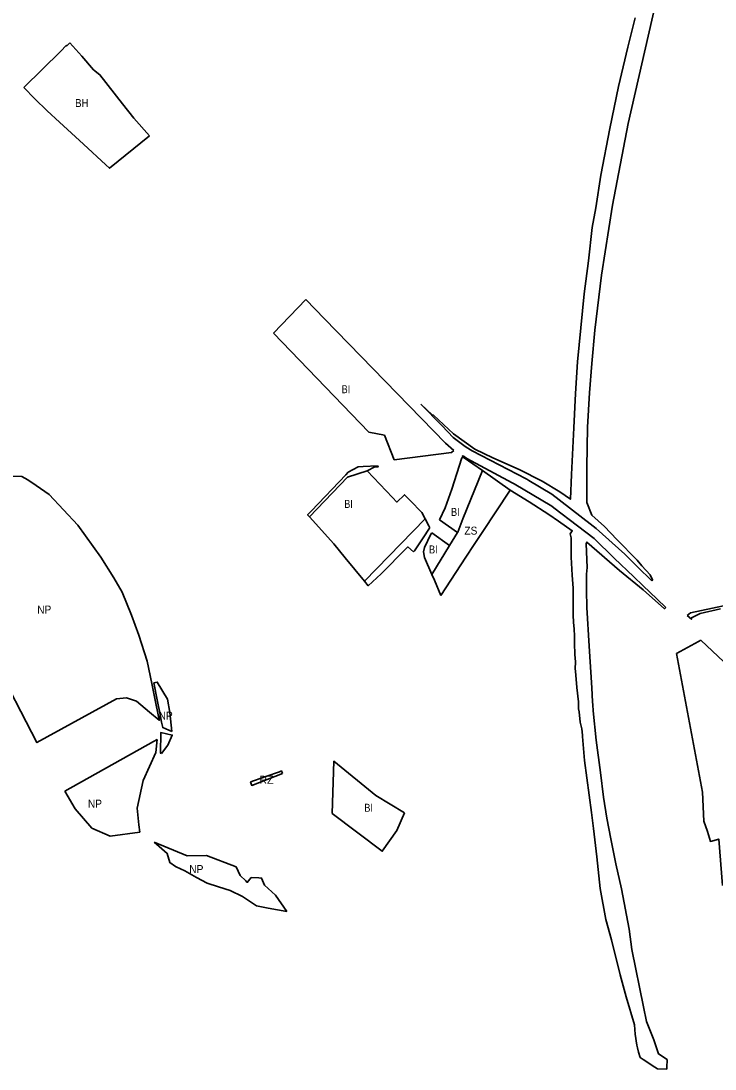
# Model space of a CAD drawing. Extents: x -650971 to -642489, y -1074311 to -1062745.
# Drawn here: x -646196 to -645155, y -1073293 to -1071722 of the extents above; entities that cross this region are included whole.
import ezdxf

# ---------------------------------------------------------------- set-up
doc = ezdxf.new("R2010")
doc.units = 0
doc.header["$LTSCALE"] = 4.8
for name, color, linetype, lineweight in [('1', 7, 'Continuous', 35), ('15', 7, 'Continuous', 35), ('19', 7, 'Continuous', 35), ('2', 7, 'Continuous', 35), ('24', 7, 'Continuous', 35), ('41', 7, 'Continuous', 35), ('48', 7, 'Continuous', 35), ('6', 7, 'Continuous', 35), ('62', 7, 'Continuous', 35)]:
    doc.layers.add(name, color=color, linetype=linetype, lineweight=lineweight)

msp = doc.modelspace()

# ---------------------------------------------------------------- linework, layer by layer
at = {"layer": '1'}
for points in [[(-646191.57, -1071821.44), (-646136.12, -1071767.07), (-646127.84, -1071758.53), (-646127.12, -1071759.15), (-646122.16, -1071754.78)], [(-646122.16, -1071754.78), (-646104.5, -1071774.86), (-646087, -1071795), (-646077.32, -1071802.59), (-646043.49, -1071845.87), (-646026.64, -1071867.44), (-646002.93, -1071893.984)], [(-646068.317, -1071937.555), (-646102.04, -1071906.4), (-646137.74, -1071873.31), (-646156.59, -1071856.53), (-646174.69, -1071838.69), (-646191.57, -1071821.44)], [(-646002.93, -1071893.984), (-646062.91, -1071942.55), (-646068.317, -1071937.555)]]:
    msp.add_lwpolyline(points, dxfattribs=at)
at = {"layer": '15'}
for p, q in [((-645680.87, -1072561.42), (-645589.862, -1072468.109)), ((-645197.044, -1072612.821), (-645192.06, -1072609.19))]:
    msp.add_line(p, q, dxfattribs=at)
for points in [[(-645763.06, -1072465.26), (-645765.95, -1072462.03), (-645760.02, -1072455.94), (-645708.94, -1072402.11), (-645705, -1072398.19), (-645690.37, -1072390.13), (-645682.59, -1072389.76), (-645661.3, -1072388.74)], [(-645661.3, -1072388.74), (-645660.16, -1072389.95), (-645665.32, -1072390.32), (-645676.53, -1072396.16)], [(-645676.53, -1072396.16), (-645706.039, -1072405.769), (-645763.06, -1072465.26)], [(-645589.862, -1072468.109), (-645584.46, -1072478.58), (-645582.84, -1072481.71)], [(-645582.84, -1072481.71), (-645583.13, -1072482.13), (-645592.9, -1072496.52), (-645604.82, -1072514.3), (-645605.95, -1072515.95), (-645607.07, -1072517.61)], [(-645607.07, -1072517.61), (-645615.95, -1072510.16), (-645617.87, -1072512.12), (-645655.65, -1072550.62), (-645675.13, -1072568.36), (-645680.87, -1072561.42)], [(-645192.06, -1072609.19), (-645102.73, -1072589.74), (-644999.72, -1072564.24), (-644978.56, -1072558.74), (-644967.97, -1072556.17), (-644954.57, -1072554.43), (-644946.57, -1072554.22), (-644926.81, -1072552.51)], [(-645147.13, -1072602.79), (-645177.56, -1072609.89), (-645179.6, -1072610.94), (-645190.59, -1072616.28), (-645190.71, -1072618.6), (-645197.044, -1072612.821)]]:
    msp.add_lwpolyline(points, dxfattribs=at)
at = {"layer": '19'}
for points in [[(-645213.34, -1072669.98), (-645180.05, -1072651.77), (-645176.71, -1072650.01)], [(-645176.71, -1072650.01), (-645142.1, -1072682.57), (-645133.26, -1072694.17), (-645121.96, -1072711.68), (-645076.66, -1072783.06)], [(-645144.37, -1073017.64), (-645149.84, -1072948.13), (-645162.379, -1072951.55), (-645166.48, -1072936.5), (-645172.28, -1072921.42), (-645174.13, -1072877.93), (-645213.34, -1072669.98)]]:
    msp.add_lwpolyline(points, dxfattribs=at)
at = {"layer": '2'}
msp.add_line((-645817.219, -1072189.975), (-645768.649, -1072139.283), dxfattribs=at)
for points in [[(-645768.649, -1072139.283), (-645740.45, -1072168.23), (-645559.34, -1072354.42), (-645546.82, -1072365.72)], [(-645636.37, -1072379.57), (-645650.78, -1072342.73), (-645674, -1072338), (-645817.219, -1072189.975)], [(-645546.82, -1072365.72), (-645550.41, -1072368.47), (-645636.37, -1072379.57)], [(-645568.38, -1072469.68), (-645559.92, -1072451.41), (-645549.6, -1072423.39), (-645535.05, -1072376.72), (-645532.75, -1072375.41), (-645503.98, -1072395.64)], [(-645763.06, -1072465.26), (-645706.039, -1072405.769), (-645676.53, -1072396.16)], [(-645676.53, -1072396.16), (-645638.82, -1072435.99), (-645632.1, -1072442.93), (-645620.56, -1072432), (-645609.99, -1072443.22), (-645597.15, -1072456.15), (-645597.122, -1072456.121), (-645594.83, -1072458.48), (-645589.862, -1072468.109), (-645680.87, -1072561.42)], [(-645503.98, -1072395.64), (-645533.15, -1072468.21), (-645541.09, -1072487.98), (-645541.56, -1072488.74), (-645568.38, -1072469.68)], [(-645680.87, -1072561.42), (-645709.92, -1072526.3), (-645726.95, -1072505.7), (-645763.06, -1072465.26)], [(-645579.76, -1072551.45), (-645591.03, -1072526.14), (-645592.08, -1072517.43), (-645591.06, -1072511.06), (-645581.13, -1072491), (-645579.92, -1072489.22)], [(-645579.92, -1072489.22), (-645553.35, -1072508.1), (-645579.76, -1072551.45)], [(-645729.36, -1072909.65), (-645726.9, -1072831.5), (-645663.52, -1072882.58), (-645620.92, -1072908.65)], [(-645620.92, -1072908.65), (-645632.23, -1072935.28), (-645654.16, -1072966.3), (-645729.36, -1072909.65)]]:
    msp.add_lwpolyline(points, dxfattribs=at)
at = {"layer": '24'}
for points in [[(-645244.798, -1071696.585), (-645285.617, -1071875.733), (-645309.01, -1071998.147), (-645325.498, -1072102.789), (-645335.367, -1072185.207), (-645339.908, -1072235.158), (-645343.458, -1072278.998), (-645346.62, -1072330.914), (-645347.677, -1072391.355), (-645347.551, -1072443.527), (-645339.904, -1072462.677), (-645320.805, -1072479.495), (-645302.303, -1072499.014), (-645272.276, -1072530.154), (-645265.009, -1072538.358)], [(-645596.405, -1072296.114), (-645579.217, -1072312.425), (-645577.33, -1072312.704), (-645547.593, -1072340.827), (-645515.437, -1072363.447), (-645488.64, -1072376.782), (-645448.831, -1072394.325), (-645414.631, -1072411.611), (-645387.894, -1072427.453), (-645372.228, -1072438.764), (-645370.624, -1072401.447), (-645366.951, -1072331.609), (-645364.435, -1072280.268), (-645361.317, -1072232.824), (-645351.358, -1072130.815), (-645344.819, -1072081.225), (-645339.455, -1072031.565), (-645334.118, -1072001.954), (-645326.343, -1071952.807), (-645313.153, -1071883.081), (-645300.076, -1071820.179), (-645286.175, -1071761.228), (-645274.868, -1071717.176)], [(-645249.9, -1072561.25), (-645271.74, -1072539.96), (-645290.76, -1072520.92), (-645333.62, -1072482.33), (-645342.284, -1072475.625), (-645399.77, -1072431.12), (-645434.19, -1072410.67), (-645437.6, -1072408.64), (-645438.64, -1072408.1), (-645519.57, -1072366.3), (-645528.27, -1072360.53), (-645531.65, -1072358.29), (-645532.07, -1072358.01), (-645547.72, -1072346.19), (-645564.4, -1072328.61), (-645596.405, -1072296.114)], [(-645532.75, -1072375.41), (-645534.3, -1072374.33), (-645533.08, -1072373.71)], [(-645533.08, -1072373.71), (-645527.33, -1072377.73), (-645459.31, -1072413.95), (-645456.52, -1072415.6), (-645400.12, -1072449.03), (-645396.94, -1072451.44), (-645361.47, -1072478.388), (-645336.33, -1072497.48), (-645306.46, -1072527.08), (-645276.93, -1072555.11), (-645263.7, -1072567.8), (-645242, -1072588.6), (-645228.96, -1072600.865)], [(-645462.651, -1072425.011), (-645462.65, -1072425.01), (-645503.98, -1072395.64), (-645532.75, -1072375.41)], [(-645359.825, -1072751.964), (-645359.96, -1072742.38), (-645362.37, -1072720.66), (-645364.5, -1072696.22), (-645364.786, -1072692.977), (-645364.524, -1072682.575), (-645365.24, -1072671.66), (-645366.02, -1072654.46), (-645366.09, -1072643.58), (-645366.41, -1072633.54), (-645367.25, -1072622.73), (-645368.04, -1072612.42), (-645367.78, -1072602.42), (-645368.173, -1072571.881), (-645369.31, -1072552.64), (-645370.22, -1072543.37), (-645370.755, -1072525.734), (-645370.928, -1072496.619), (-645372.72, -1072490.314), (-645369.364, -1072485.931), (-645389.731, -1072471.612), (-645404.64, -1072461.72), (-645433.91, -1072442.56), (-645462.651, -1072425.011)], [(-645228.96, -1072600.865), (-645230.845, -1072602.888), (-645263.217, -1072574.314), (-645298.498, -1072545.352), (-645347.292, -1072502.877), (-645348.253, -1072505.583), (-645347.214, -1072540.97), (-645347.88, -1072551.13), (-645347.795, -1072577.893), (-645347.37, -1072597.96), (-645347.3, -1072601.13), (-645344.152, -1072658.857), (-645339.96, -1072721.587), (-645338.778, -1072742.565), (-645338.538, -1072746.821)], [(-645265.009, -1072538.358), (-645252.768, -1072552.178), (-645248.967, -1072559.511), (-645249.9, -1072561.25)], [(-645338.538, -1072746.821), (-645338.023, -1072755.969), (-645333.718, -1072799.987), (-645327.091, -1072848.387), (-645322.284, -1072885.085), (-645317.65, -1072916.642), (-645311.772, -1072947.945), (-645304.24, -1072985.372), (-645295.788, -1073022.556), (-645284.269, -1073083.286), (-645279.878, -1073113.356), (-645262.388, -1073199.409), (-645257.842, -1073221.36), (-645247.051, -1073248.736), (-645239.9, -1073270.025), (-645226.847, -1073278.345)], [(-645359.179, -1072757.517), (-645359.76, -1072752.865), (-645359.825, -1072751.964)], [(-645355.121, -1072782.993), (-645357.272, -1072772.771), (-645359.179, -1072757.517)], [(-645353.861, -1072794.334), (-645354.019, -1072792.454), (-645355.121, -1072782.993)], [(-645332.517, -1072974.538), (-645337.34, -1072932.073), (-645340.345, -1072908.029), (-645350.822, -1072830.388), (-645353.86, -1072794.339), (-645353.861, -1072794.334)], [(-645310.558, -1073098.946), (-645319.052, -1073068.6), (-645327.554, -1073022.214), (-645332.517, -1072974.538)], [(-645272.747, -1073256.762), (-645275.269, -1073240.71), (-645276.125, -1073226.571), (-645288.647, -1073184.518), (-645297.395, -1073151.294), (-645310.558, -1073098.946)], [(-645267.53, -1073275.44), (-645269.83, -1073267.22), (-645271.52, -1073261.16), (-645272.747, -1073256.762)], [(-645227.744, -1073292.736), (-645241.72, -1073292.2), (-645245.5, -1073289.73), (-645263.03, -1073278.25), (-645267.53, -1073275.44)], [(-645226.847, -1073278.345), (-645227.199, -1073283.366), (-645227.35, -1073285.55), (-645227.744, -1073292.736)]]:
    msp.add_lwpolyline(points, dxfattribs=at)
at = {"layer": '41'}
for points in [[(-645541.56, -1072488.74), (-645541.09, -1072487.98), (-645533.15, -1072468.21), (-645503.98, -1072395.64)], [(-645503.98, -1072395.64), (-645462.65, -1072425.01), (-645462.651, -1072425.011)], [(-645462.651, -1072425.011), (-645504.48, -1072488.58), (-645516.37, -1072506.64), (-645528.81, -1072525.54), (-645566.54, -1072582.88)], [(-645579.76, -1072551.45), (-645553.35, -1072508.1), (-645541.56, -1072488.74)], [(-645566.54, -1072582.88), (-645575.9, -1072560.13), (-645579.76, -1072551.45)]]:
    msp.add_lwpolyline(points, dxfattribs=at)
at = {"layer": '48'}
for points in [[(-646237.94, -1072404.35), (-646194.19, -1072404.62), (-646185.45, -1072409.47), (-646172.81, -1072418.2), (-646153.49, -1072431.54), (-646110.61, -1072477.49), (-646075.82, -1072525.54), (-646056.42, -1072556.49), (-646043.87, -1072578.12), (-646030.17, -1072612.31), (-646019.16, -1072642.35), (-646006.66, -1072681.4), (-645999.25, -1072714.68), (-645993.89, -1072742.23), (-645990.04, -1072761.78), (-645988.43, -1072769.93), (-646003.22, -1072757.85), (-646022.4, -1072741.58), (-646037.23, -1072736.38), (-646052.58, -1072737.82), (-646171.72, -1072803.51), (-646236.97, -1072678.31)], [(-646129.91, -1072876.24), (-645996.8, -1072801.88), (-645991.37, -1072798.84)], [(-645991.37, -1072798.84), (-645993.47, -1072818.44), (-646012.37, -1072860.3), (-646021.64, -1072901.6), (-646019.21, -1072926.91), (-646017.65, -1072937.59)], [(-646089.39, -1072931.92), (-646114.5, -1072902.8), (-646129.91, -1072876.24)], [(-646017.65, -1072937.59), (-646062.04, -1072943.58), (-646089.39, -1072931.92)], [(-645996.2, -1072952.69), (-645946.4, -1072973.05), (-645917.53, -1072972.93), (-645873.3, -1072989.79), (-645866.93, -1073002.72), (-645858.82, -1073010.74), (-645856.46, -1073013.07), (-645850.37, -1073005.42), (-645838.89, -1073006.18), (-645834.9, -1073006.45), (-645830.6, -1073016.92), (-645814.27, -1073032.11), (-645797.32, -1073056.62)], [(-645797.32, -1073056.62), (-645824.93, -1073051.83), (-645842.53, -1073048.19), (-645863.39, -1073034.25), (-645882.07, -1073025.22), (-645899.35, -1073019.65), (-645916.47, -1073014.03), (-645932.44, -1073005.5), (-645949.85, -1072995.57), (-645962.81, -1072989.45), (-645963.77, -1072989), (-645972.6, -1072983.41), (-645976.48, -1072969.55), (-645988.49, -1072959.28), (-645996.2, -1072952.69)]]:
    msp.add_lwpolyline(points, dxfattribs=at)
for points in [[(-645969.46, -1072787.03), (-645983.22, -1072780.88), (-645984.79, -1072772.91), (-645987.1, -1072761.2), (-645990.95, -1072741.65), (-645996.31, -1072714.11), (-645991.31, -1072712.86), (-645975.86, -1072738.61), (-645972.31, -1072758.48)], [(-645985.19, -1072819.72), (-645986.71, -1072819.26), (-645986.24, -1072788.33), (-645969.01, -1072792.28), (-645975.3, -1072807.37)]]:
    msp.add_lwpolyline(points, close=True, dxfattribs=at)
at = {"layer": '6'}
for points in [[(-645849.705, -1072867.618), (-645851.48, -1072862.586), (-645848.628, -1072861.433), (-645845.619, -1072860.364), (-645842.74, -1072859.344), (-645839.908, -1072858.343), (-645837.027, -1072857.313), (-645834.208, -1072856.314), (-645828.409, -1072854.254), (-645825.527, -1072853.233), (-645822.726, -1072852.233), (-645819.779, -1072851.184), (-645816.948, -1072850.184), (-645813.978, -1072849.124), (-645811.148, -1072848.124), (-645808.177, -1072847.063), (-645805.159, -1072845.994), (-645803.84, -1072849.72)], [(-645803.84, -1072849.72), (-645849.703, -1072867.622), (-645849.705, -1072867.618)]]:
    msp.add_lwpolyline(points, dxfattribs=at)

# ---------------------------------------------------------------- texts
at = {"layer": '62'}
for s, width, p in [('BH', 0.9, (-646114.48, -1071850.818)), ('BI', 0.85, (-645715.06, -1072279.771)), ('BI', 0.85, (-645711.104, -1072451.727)), ('BI', 0.85, (-645551.06, -1072463.771)), ('ZS', 0.95, (-645531.06, -1072491.771)), ('BI', 0.85, (-645584, -1072520)), ('NP', 0.95, (-646171.335, -1072610.048)), ('NP', 0.95, (-645989.335, -1072769.048)), ('NP', 0.95, (-646095.335, -1072901.048)), ('BI', 0.85, (-645681, -1072907.167)), ('NP', 0.95, (-645943.335, -1072999.048))]:
    msp.add_text(s, height=12, dxfattribs=dict(at, width=width)).set_placement(p)
msp.add_text('RZ', height=12, dxfattribs=at).set_placement((-645838.415, -1072865.224))

doc.saveas('drawing.dxf')
